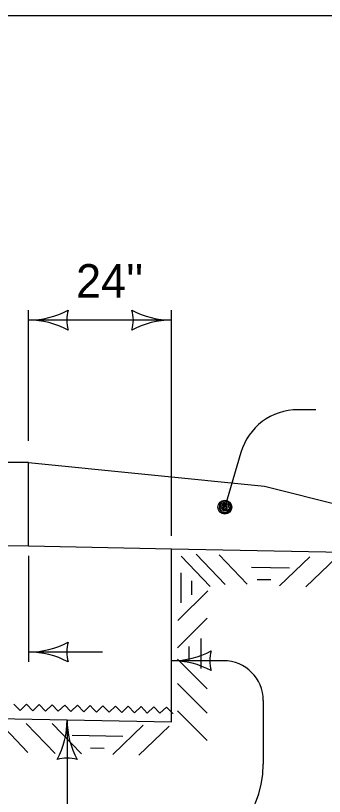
# Model space of a CAD drawing. Extents: x 9234 to 81668, y 5635 to 15999.
# Drawn here: x 18209 to 18355.9, y 9572.3 to 9944 of the extents above; entities that cross this region are included whole.
import ezdxf

# ---------------------------------------------------------------- set-up
doc = ezdxf.new("R2010")
doc.units = 0
for name, color, linetype in [('Level 61', 7, 'Continuous'), ('PS_CONST', 7, 'Continuous'), ('PS_DAWA', 7, 'Continuous'), ('PS_DIM', 7, 'Continuous')]:
    doc.layers.add(name, color=color, linetype=linetype)

msp = doc.modelspace()

# ---------------------------------------------------------------- linework, layer by layer
at = {"layer": 'Level 61'}
msp.add_lwpolyline([(17332.52, 9944.02), (20467.53, 9944.02), (20467.53, 7924.02), (17332.52, 7924.02)], close=True, dxfattribs=at)
at = {"layer": 'PS_CONST'}
for p, q in [((18351.78, 9756.42), (18343.4, 9756.42)), ((18316.18, 9736), (18308.59, 9710)), ((18307.93, 9636.92), (18283.21, 9636.92)), ((18326.84, 9618.01), (18326.84, 9587.65)), ((18233.53, 9608.75), (18233.53, 9568.74))]:
    msp.add_line(p, q, dxfattribs=at)
msp.add_lwpolyline([(18308.33, 9706.96), (18309.45, 9707.47), (18311.19, 9708.01), (18311.52, 9709.77), (18311.28, 9711.32), (18310.17, 9712.75), (18308.52, 9712.6), (18306.78, 9712.35), (18305.94, 9710.97), (18305.79, 9709.5), (18306.82, 9707.59), (18308.09, 9707.43), (18309.83, 9707.87), (18311.25, 9708.98), (18311.21, 9710.63), (18310.1, 9711.97), (18308.54, 9712.11), (18306.79, 9711.77), (18306.53, 9710.79), (18306.18, 9709.61), (18307, 9708.18), (18308.26, 9708.21), (18309.72, 9708.45), (18310.76, 9709.26), (18310.23, 9710.7), (18309.14, 9711.55), (18307.68, 9711.6), (18307.31, 9710.81), (18306.85, 9709.92), (18307.56, 9708.78), (18308.64, 9708.52), (18309.6, 9709.03), (18309.67, 9710.1), (18309.16, 9710.86), (18308.18, 9711.13), (18307.7, 9710.73), (18307.43, 9710.14), (18307.94, 9709.27), (18308.62, 9709.1), (18309.3, 9709.51), (18309.18, 9710.09), (18308.68, 9710.47), (18308, 9710.45), (18308.02, 9709.96), (18308.61, 9709.68)], dxfattribs=at)
msp.add_circle((18308.59, 9710), 3.31, dxfattribs=at)
for centre, radius, start, end in [((18343.4, 9728.06), 28.36, 90, 163.739), ((18283.22, 9677.09), 40.18, 270, 298.0725), ((18316.9, 9636.92), 15.52, 162.2666, 197.7334), ((18283.22, 9596.74), 40.18, 61.9275, 90), ((18307.94, 9618.01), 18.91, 0, 90), ((18193.35, 9608.75), 40.18, 331.9275, 360), ((18273.71, 9608.75), 40.18, 180, 208.0725), ((18233.53, 9575.06), 15.52, 72.2666, 107.7334), ((18279.58, 9587.65), 47.27, 270, 360)]:
    msp.add_arc(centre, radius, start, end, dxfattribs=at)
at = {"layer": 'PS_DAWA'}
for p, q in [((18215.16, 9741.65), (18215.16, 9803.8)), ((18283.21, 9696.3), (18283.21, 9803.8)), ((18283.21, 9799.07), (18215.16, 9799.07)), ((18215.16, 9686.81), (18215.16, 9636.32)), ((18250.37, 9641.04), (18215.16, 9641.04))]:
    msp.add_line(p, q, dxfattribs=at)
for centre, radius, start, end in [((18215.15, 9839.25), 40.18, 270, 298.0725), ((18248.84, 9799.07), 15.52, 162.2666, 197.7334), ((18249.53, 9799.07), 15.52, 342.2666, 17.7334), ((18283.22, 9839.25), 40.18, 241.9275, 270), ((18215.15, 9758.9), 40.18, 61.9275, 90), ((18283.22, 9758.9), 40.18, 90, 118.0725), ((18215.15, 9681.22), 40.18, 270, 298.0725), ((18248.84, 9641.05), 15.52, 162.2666, 197.7334), ((18215.15, 9600.87), 40.18, 61.9275, 90)]:
    msp.add_arc(centre, radius, start, end, dxfattribs=at)
at = {"layer": 'PS_DIM'}
for p, q in [((18215.16, 9731.25), (18202.39, 9731.25)), ((18215.16, 9731.25), (18202.39, 9731.25)), ((18215.16, 9691.54), (18215.16, 9731.25)), ((18215.16, 9691.54), (18215.16, 9731.25)), ((18215.16, 9731.25), (18327.43, 9720.02)), ((18327.43, 9720.02), (18503.11, 9676.09)), ((17466.05, 9706.58), (18215.16, 9691.54)), ((17467.19, 9706.55), (18215.16, 9691.54)), ((18215.16, 9691.54), (18283.21, 9690.17)), ((18283.21, 9607.75), (18283.21, 9690.17)), ((18283.21, 9690.17), (18461.07, 9686.6)), ((18287.71, 9686.69), (18301.57, 9672.27)), ((18294.93, 9687.63), (18308.79, 9673.2)), ((18305.79, 9687.29), (18319.17, 9673.37)), ((18349, 9686.43), (18334.58, 9672.57)), ((18361.45, 9685.95), (18347.02, 9672.09)), ((18286.25, 9656.07), (18300.39, 9670.21)), ((18286.02, 9643.06), (18300.16, 9657.2)), ((18286.02, 9637.65), (18300.16, 9623.51)), ((17466.62, 9624.14), (18283.21, 9607.75)), ((18286.02, 9626.08), (18300.16, 9611.93)), ((18286.02, 9613.01), (18300.16, 9598.87)), ((18201.01, 9607.59), (18214.86, 9593.16)), ((18214.01, 9607.1), (18227.87, 9592.68)), ((18226.46, 9607.08), (18240.32, 9592.65)), ((18269.68, 9606.21), (18255.25, 9592.35)), ((18282.12, 9605.73), (18267.7, 9591.88))]:
    msp.add_line(p, q, dxfattribs=at)
for points in [[(18321.25, 9681.51), (18339.31, 9681.14)], [(18287.83, 9664.51), (18287.83, 9678.7)], [(18323.9, 9675.65), (18330.43, 9675.52)], [(18292.92, 9668.34), (18292.92, 9674.87)], [(18297.37, 9633.26), (18297.37, 9647.45)], [(18291.52, 9637.09), (18291.52, 9643.62)], [(18208.19, 9616.3), (18211.15, 9613.21), (18214.24, 9616.18), (18217.2, 9613.09), (18220.29, 9616.06), (18223.25, 9612.97), (18226.34, 9615.93), (18229.3, 9612.85), (18232.38, 9615.81), (18235.35, 9612.73), (18238.43, 9615.69), (18241.4, 9612.61), (18244.48, 9615.57), (18245.96, 9614.03)], [(18245.96, 9614.03), (18247.45, 9612.49), (18250.53, 9615.45), (18253.5, 9612.36), (18256.58, 9615.32), (18259.54, 9612.24), (18262.63, 9615.21), (18265.59, 9612.12), (18268.68, 9615.09), (18271.64, 9612), (18274.73, 9614.96), (18277.69, 9611.88), (18280.78, 9614.84), (18283.74, 9611.75), (18283.96, 9611.94)], [(18235.93, 9601.41), (18259.99, 9600.93)], [(18244.58, 9595.44), (18251.11, 9595.3)]]:
    msp.add_lwpolyline(points, dxfattribs=at)

# ---------------------------------------------------------------- texts
at = {"layer": 'PS_DAWA'}
msp.add_text("24''", height=16, dxfattribs=at).set_placement((18237.79, 9809.71))

doc.saveas('drawing.dxf')
